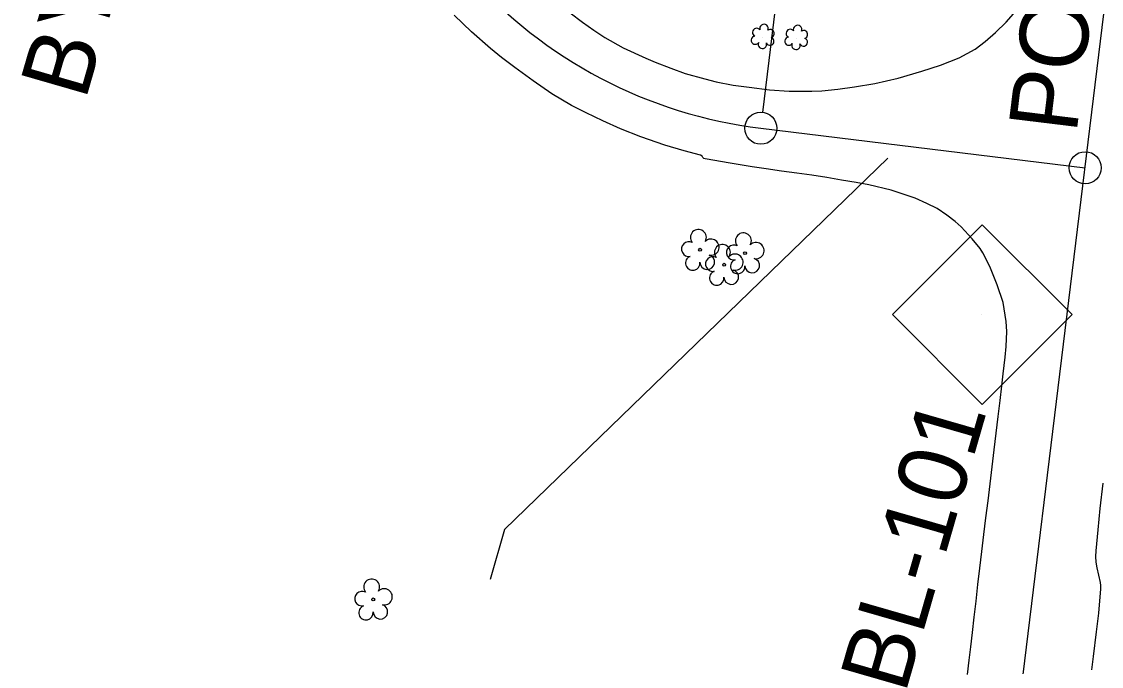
# Model space of a CAD drawing. Extents: x 479429 to 482809, y 488118 to 492379.
# Drawn here: x 481109.2 to 481361.5, y 490710.2 to 490861 of the extents above; entities that cross this region are included whole.
import ezdxf

# ---------------------------------------------------------------- set-up
doc = ezdxf.new("R2010")
doc.units = 0
for name, color, linetype in [('CTL Secondary Horizontal and Vertical CELL', 7, 'Continuous'), ('CTL Secondary Horizontal and Vertical Leader', 7, 'Continuous'), ('CTL Secondary Horizontal and Vertical Text', 7, 'Continuous'), ('Exist Horizontal Alignment', 7, 'Continuous'), ('Exist Roads EOP', 7, 'Continuous'), ('Exist Vegetation Shrub CELL', 7, 'Continuous'), ('Exist Vegetation Tree CELL', 7, 'Continuous')]:
    doc.layers.add(name, color=color, linetype=linetype)

msp = doc.modelspace()

# ---------------------------------------------------------------- linework, layer by layer
at = {"layer": 'CTL Secondary Horizontal and Vertical CELL'}
msp.add_line((481333.52, 490792.44), (481333.52, 490792.44), dxfattribs=at)
msp.add_lwpolyline([(481312.66, 490792.51), (481333.63, 490813.48), (481354.63, 490792.48), (481333.66, 490771.51)], close=True, dxfattribs=at)
at = {"layer": 'CTL Secondary Horizontal and Vertical Leader'}
msp.add_lwpolyline([(481311.62, 490829.06), (481222.05, 490742.21), (481218.67, 490730.58)], dxfattribs=at)
at = {"layer": 'Exist Horizontal Alignment'}
for p, q in [((481201.31, 489545.89), (481397.95, 491156.7)), ((481282.37, 490839.78), (481290.26, 490904.44)), ((481281.92, 490836.06), (481357.68, 490826.82))]:
    msp.add_line(p, q, dxfattribs=at)
for centre in [(481281.92, 490836.06), (481357.68, 490826.82)]:
    msp.add_circle(centre, 3.75, dxfattribs=at)
msp.add_arc((481295.08, 490943.97), 108.71, 221.4386, 263.0452, dxfattribs=at)
at = {"layer": 'Exist Roads EOP'}
for points in [[(481237.36, 490863.01), (481240.21, 490860.89), (481242.9, 490858.97), (481245.47, 490857.24), (481249.73, 490854.89), (481255.05, 490852.41), (481257.26, 490851.5), (481260.88, 490850.1), (481264.26, 490848.9), (481268.85, 490847.58), (481271.5, 490846.93), (481275.42, 490846.16), (481279.16, 490845.64), (481283.95, 490845.07), (481288.55, 490844.77), (481293.83, 490844.73), (481296.19, 490844.81), (481299.89, 490845.18), (481303.77, 490845.73), (481308.56, 490846.56), (481313.97, 490847.8), (481319.5, 490849.37), (481323.89, 490850.79), (481328.22, 490852.56), (481331.97, 490854.57), (481334.36, 490856.34), (481336.75, 490858.41), (481339.23, 490860.83), (481341.48, 490863.41)], [(481330.21, 490708.31), (481330.6, 490711.69), (481330.96, 490714.84), (481331.35, 490718.19), (481331.76, 490721.74), (481332.19, 490725.49), (481332.65, 490729.36), (481333.11, 490733.24), (481333.57, 490737.14), (481334.04, 490741.05), (481334.52, 490744.99), (481335, 490748.95), (481335.48, 490752.93), (481335.96, 490756.93), (481336.44, 490760.9), (481336.9, 490764.8), (481337.37, 490768.63), (481337.82, 490772.39), (481338.23, 490775.82), (481338.56, 490778.66), (481339, 490782.56), (481339.23, 490785.02), (481339.41, 490788.55), (481339.27, 490790.85), (481338.55, 490795.3), (481337.14, 490799.48), (481335.39, 490803.76), (481333.81, 490806.91), (481333.14, 490807.91), (481331.32, 490810.21), (481328.73, 490812.99), (481327.29, 490814.29), (481325.4, 490815.74), (481323.08, 490817.26), (481320.73, 490818.48), (481317.96, 490819.68), (481312.33, 490821.59), (481307.18, 490822.82), (481304.2, 490823.36), (481300.78, 490823.95), (481297.31, 490824.52), (481293.81, 490825.07), (481290.29, 490825.55), (481286.75, 490826.03), (481283.18, 490826.55), (481279.89, 490827.05), (481274.72, 490827.91), (481268.9, 490828.93), (481268.62, 490829), (481268.34, 490829.21), (481268.22, 490829.54), (481267.82, 490829.74), (481263.97, 490830.8), (481259.51, 490832.12), (481253.89, 490834.04), (481249.09, 490835.94), (481244.96, 490837.8), (481241.1, 490839.67), (481237.67, 490841.41), (481233.04, 490844.14), (481228.68, 490847.12), (481224.43, 490850.23), (481221.31, 490852.64), (481218.74, 490854.68), (481214.28, 490858.58), (481210.26, 490862.5)], [(481361.82, 490753.07), (481361.15, 490747.19), (481360.62, 490742.18), (481360.15, 490737.29), (481360.12, 490735.92), (481360.21, 490734.58), (481360.39, 490733.26), (481361.21, 490729.86), (481361.29, 490729.15), (481361.31, 490728.35), (481360.77, 490722.7), (481360.26, 490718.33), (481359.57, 490712.52), (481359.2, 490709.41)]]:
    msp.add_lwpolyline(points, dxfattribs=at)
at = {"layer": 'Exist Vegetation Shrub CELL'}
for p, q in [((481282.41, 490857.34), (481282.41, 490857.34)), ((481290.26, 490857.11), (481290.26, 490857.11))]:
    msp.add_line(p, q, dxfattribs=at)
for centre, radius, start, end in [((481282.64, 490859.38), 0.99, 334.8391, 200.4717), ((481280.93, 490858.47), 0.968, 35.8908, 245.4216), ((481284.08, 490858.21), 0.929, 284.4567, 126.0861), ((481288.78, 490858.24), 0.968, 35.8908, 245.4216), ((481290.49, 490859.15), 0.99, 334.8391, 200.4717), ((481291.93, 490857.98), 0.929, 284.4567, 126.0861), ((481280.61, 490856.64), 0.955, 95.1099, 327.9534), ((481282.28, 490855.66), 0.984, 151.2797, 21.387), ((481284.05, 490856.41), 0.937, 204.9913, 73.4601), ((481288.46, 490856.41), 0.955, 95.1099, 327.9534), ((481290.13, 490855.43), 0.984, 151.2797, 21.387), ((481291.9, 490856.18), 0.937, 204.9913, 73.4601)]:
    msp.add_arc(centre, radius, start, end, dxfattribs=at)
at = {"layer": 'Exist Vegetation Tree CELL'}
for p, q in [((481267.71, 490807.66), (481267.71, 490807.66)), ((481278.22, 490806.86), (481278.22, 490806.86)), ((481273.32, 490804.16), (481273.32, 490804.16)), ((481191.36, 490725.91), (481191.36, 490725.91))]:
    msp.add_line(p, q, dxfattribs=at)
for centre in [(481267.71, 490807.66), (481278.22, 490806.86), (481273.32, 490804.16), (481191.36, 490725.91)]:
    msp.add_circle(centre, 0.326, dxfattribs=at)
for centre, radius, start, end in [((481267.33, 490810.53), 1.86, 330.1651, 219.7134), ((481270.26, 490808.25), 1.9, 257.1011, 134.1999), ((481277.84, 490809.74), 1.86, 330.1651, 219.7134), ((481265.11, 490807.81), 1.73, 62.6636, 279.3457), ((481272.94, 490807.03), 1.86, 330.1651, 219.7134), ((481275.62, 490807.02), 1.73, 62.6636, 279.3457), ((481280.77, 490807.45), 1.9, 257.1011, 134.1999), ((481266.01, 490804.54), 1.69, 111.5671, 6.231), ((481269.39, 490804.76), 1.7, 181.2822, 74.56), ((481270.72, 490804.31), 1.73, 62.6636, 279.3457), ((481275.87, 490804.75), 1.9, 257.1011, 134.1999), ((481276.52, 490803.74), 1.69, 111.5671, 6.231), ((481279.9, 490803.96), 1.7, 181.2822, 74.56), ((481271.62, 490801.04), 1.69, 111.5671, 6.231), ((481275, 490801.26), 1.7, 181.2822, 74.56), ((481190.98, 490728.79), 1.86, 330.1651, 219.7134), ((481188.76, 490726.07), 1.73, 62.6636, 279.3457), ((481193.91, 490726.5), 1.9, 257.1011, 134.1999), ((481189.66, 490722.79), 1.69, 111.5671, 6.231), ((481193.04, 490723.01), 1.7, 181.2822, 74.56)]:
    msp.add_arc(centre, radius, start, end, dxfattribs=at)

# ---------------------------------------------------------------- texts
at = {"layer": 'CTL Secondary Horizontal and Vertical Text'}
for s, p in [('BY1-127', (481124.08, 490842.35)), ('BL-101', (481315.61, 490703.6))]:
    msp.add_text(s, height=16, rotation=73.904, dxfattribs=at).set_placement(p)
at = {"layer": 'Exist Horizontal Alignment'}
msp.add_text('POT', height=16, rotation=83.0452, dxfattribs=at).set_placement((481355.64, 490834.63))

doc.saveas('drawing.dxf')
